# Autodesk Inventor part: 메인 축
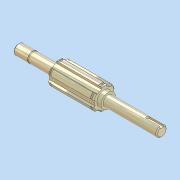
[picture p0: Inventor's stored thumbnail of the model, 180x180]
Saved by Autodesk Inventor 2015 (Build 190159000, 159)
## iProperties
Created: 2012-05
Part Number: 메인 축
Document SubType Name: 모델링
Designer: SeoGD™
Mass: 21.4462 g
Surface Area: 72.5109 cm^2
Volume: 21.4462 cm^3
Density: 1 g/cm^3
Material: 일반
Appearance: 기본값
변환 표준: STEP AP214IS
파일 이름: C:\Users\SeoGD\Desktop\?쒗뿕\硫붿씤 異?.stp
전처리기: Build: 253, Release: 2010 SP1 - Date: Wed 07/29/2009
전송 단위: 밀리미터
불확실성: 0.01
Author: SeoGD™
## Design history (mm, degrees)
sketch "스케치1"
  geometry: L1 (-69.5, 0)-(69.5, 0); L2 (69.5, 0)-(69.5, 5); L3 (69.5, 5)-(55.5, 5); L4 (55.5, 5)-(55.5, 4.8); L5 (55.5, 4.8)-(54.35, 4.8); L6 (54.35, 4.8)-(54.35, 5); L7 (54.35, 5)-(30.5, 5); L8 (30.5, 5)-(30.5, 9); L9 (30.5, 9)-(-13.5, 9); L10 (-13.5, 9)-(-13.5, 7); L11 (-13.5, 7)-(-17.5, 7); L12 (-17.5, 7)-(-17.5, 5); L13 (-17.5, 5)-(-69.5, 5); L14 (-69.5, 5)-(-69.5, 0); 2 further points
  constraints: 28 end point, 9 parallel, 4 collinear, 2 perpendicular, 1 coincident, 1 horizontal, 1 midpoint
  dimensions: "d2" = 1.15 distance between parallel lines of L6 L4; "d3" = 10 diameter of L3 L1; "d4" = 9.6 diameter of L5 L1; "d6" = 44 distance between parallel lines of L10 L8; "d7" = 4 distance between parallel lines of L12 L10; "d8" = 14 diameter of L11 L1; "d9" = 18 diameter of L9 L1; "d33" = 52 distance from line of L12.end L14; "d37" = 39 distance between parallel lines of L8 L2; "d38" = 14 distance between parallel lines of L2 L4
revolve "회전1" sketch "스케치1" stored, may be unused: angle "d10" = 90 deg
sketch "스케치2"
  geometry: L1 (2.5, 10.712)-(2.5, 8.646); L2 (-2.5, 10.712)-(-2.5, 8.646); A1 r 9 centre (0, 0) between (2.5, 8.646) and (-2.5, 8.646) reference; A2 r 11 centre (0, 0) between (2.5, 10.712) and (-2.5, 10.712); 1 further point
  constraints: 4 end point, 4 point on circle, 2 parallel, 1 centre point, 1 coincident, 1 vertical
  dimensions: "d11" = 22 diameter of A2; "d12" = 5 distance between parallel lines of L1 L2
extrude "돌출1" join sketch "스케치2" stored distance "d13" = 10; taper "d14" = 0 deg
chamfer "모따기1" distance "d15" = 1; stored, may be unused: second distance "d16" = 2, angle "d17" = 45 deg
node "작업 평면1"
node "작업 평면2"
sketch "스케치3"
  geometry: L1 (2.5, 10.712)-(2.5, 10.198); L2 (-2.5, 10.712)-(-2.5, 10.198); A1 r 11 centre (0, 0) between (2.5, 10.712) and (-2.5, 10.712) reference; A2 r 10.5 centre (0, 0) between (2.5, 10.198) and (-2.5, 10.198); 1 further point
  constraints: 4 end point, 2 point on circle, 1 centre point, 1 coincident, 1 parallel, 1 vertical
  dimensions: "d19" = 21 diameter of A2
extrude "돌출2" cut sketch "스케치3" distance "d20" = 1.35; taper "d21" = 0 deg
node "작업 평면3"
sketch "스케치4"
  geometry: L1 (-26, -5)-(-26, 5) reference; L2 (-26, 1.5)-(-12.5, 1.5); L3 (-12.5, -1.5)-(-26, -1.5); A1 r 1.5 centre (-12.5, 0) between (-12.5, -1.5) and (-12.5, 1.5); 2 further points
  constraints: 4 end point, 2 perpendicular, 2 point on circle, 2 point on line, 2 tangent, 1 centre point, 1 horizontal alignment, 1 midpoint
  dimensions: "d25" = 3 distance between parallel lines of L3 L2; "d26" = 15 dimension on A1 L1
extrude "돌출3" cut sketch "스케치4" distance "d27" = 1.8; taper "d28" = 0 deg
chamfer "모따기2" distance "d29" = 1; stored, may be unused: second distance "d30" = 2, angle "d31" = 45 deg
node "솔리드1"
node "솔리드 본체"
node "곡면 본체"
mirror "대칭1"
pattern_circular "원형 패턴1" dims "d23" = 360 deg
node "솔리드2"
other parameters: "d18" = -1.65
